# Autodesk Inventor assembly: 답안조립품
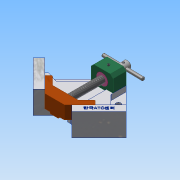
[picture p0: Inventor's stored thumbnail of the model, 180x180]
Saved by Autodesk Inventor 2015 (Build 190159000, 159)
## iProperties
Created: 2019-04
Part Number: 답안조립품
Document SubType Name: Assembly
Designer: user
Author: user
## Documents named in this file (11)
- C:\Users\user\Desktop\490407V1020\답안조립품.iam
- C:\Users\user\Desktop\490407V1020\본체.ipt
- C:\Users\user\Desktop\490407V1020\조.ipt
- C:\Users\user\Desktop\490407V1020\평행 핀 2.5x24.ipt
- C:\Users\user\Desktop\490407V1020\부시.ipt
- C:\Users\user\Desktop\490407V1020\핸들.ipt
- C:\Users\user\Desktop\490407V1020\리드스크류.ipt
- C:\Users\user\Desktop\490407V1020\서포트.ipt
- C:\Users\user\Desktop\490407V1020\멈춤나사 M4x5.ipt
- C:\Users\user\Desktop\490407V1020\멈춤나사 M4x10.ipt
- C:\Users\user\Desktop\490407V1020\볼트 M4x16.ipt
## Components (1 placed, 1 different names)
1. 핸들:1
